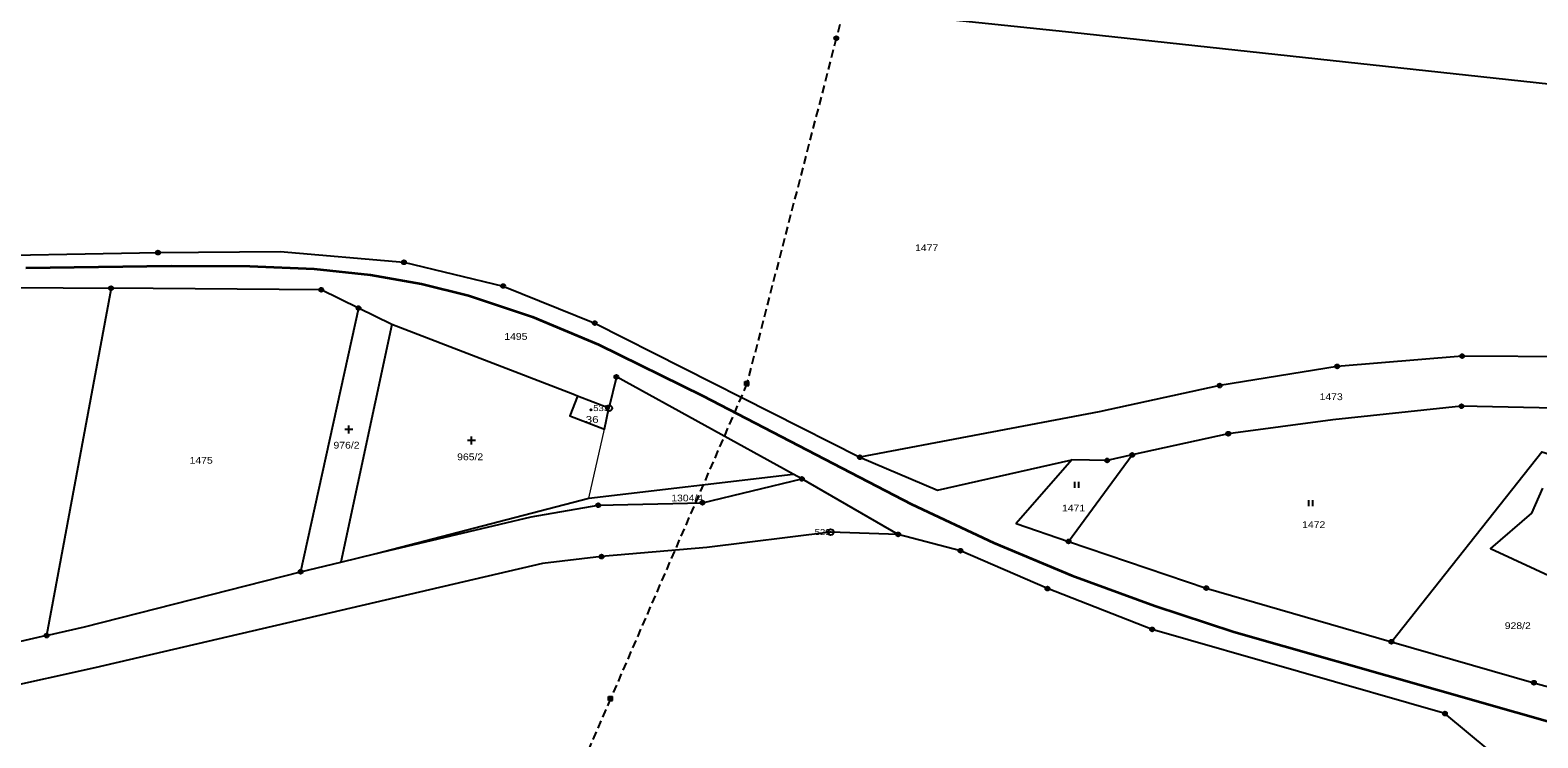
# Model space of a CAD drawing. Extents: x -872229 to -869198, y -1075981 to -1074329.
# Drawn here: x -871585.9 to -871207, y -1075387.5 to -1075209.5 of the extents above; entities that cross this region are included whole.
import ezdxf
from ezdxf.enums import TextEntityAlignment as Align

# ---------------------------------------------------------------- set-up
doc = ezdxf.new("R2010")
doc.units = 0
doc.header["$LTSCALE"] = 0.68
doc.linetypes.add('MEDIUM_DASHED', pattern=[4.5, 3, -1.5])
for name, color, linetype, lineweight in [('1', 7, 'Continuous', 25), ('3', 7, 'Continuous', 25), ('4', 7, 'Continuous', 13), ('5', 7, 'Continuous', 25), ('6', 7, 'Continuous', 25), ('8', 7, 'Continuous', 25)]:
    doc.layers.add(name, color=color, linetype=linetype, lineweight=lineweight)
doc.layers.add('2', color=7, linetype='Continuous')

msp = doc.modelspace()

# ---------------------------------------------------------------- linework, layer by layer
at = {"layer": '1'}
for p, q in [((-871391.97, -1075322.38), (-871394.16, -1075321.17)), ((-871367.76, -1075336.32), (-871391.97, -1075322.38)), ((-871517.94, -1075345.74), (-871507.87, -1075343.3))]:
    msp.add_line(p, q, dxfattribs=at)
for points in [[(-871152.53, -1075228.75), (-871324.15, -1075210.15), (-871498.95, -1075191.88), (-871564.6, -1075180.17), (-871590.36, -1075167.06), (-871608.79, -1075266.42)], [(-871673.37, -1075268.15), (-871670.8, -1075268.84), (-871646.86, -1075272.41), (-871613.89, -1075274.07), (-871565.58, -1075274.43)], [(-871608.79, -1075266.42), (-871553.79, -1075265.47), (-871523.09, -1075265.22), (-871491.97, -1075267.91), (-871467.05, -1075273.87), (-871444.01, -1075283.21), (-871377.38, -1075316.93)], [(-871503.38, -1075279.44), (-871512.76, -1075274.83), (-871565.58, -1075274.43), (-871581.77, -1075361.77)], [(-871495.01, -1075283.55), (-871503.38, -1075279.44), (-871517.94, -1075345.74)], [(-871495.01, -1075283.55), (-871507.87, -1075343.3), (-871498.97, -1075341.15)], [(-871448.37, -1075301.54), (-871449.54, -1075301.09), (-871495.01, -1075283.55)], [(-871197.94, -1075291.72), (-871226.01, -1075291.51), (-871257.41, -1075294.08), (-871286.96, -1075298.91), (-871317.28, -1075305.51), (-871377.38, -1075316.93)], [(-871394.16, -1075321.17), (-871438.58, -1075296.72), (-871440.45, -1075304.59)], [(-871198.89, -1075304.69), (-871226.19, -1075304.09), (-871258.51, -1075307.55), (-871284.79, -1075311.01), (-871308.94, -1075316.35)], [(-871243.8, -1075363.33), (-871206.01, -1075315.54), (-871202.96, -1075316.49), (-871198.89, -1075304.69)], [(-871377.38, -1075316.93), (-871357.91, -1075325.19), (-871324.12, -1075317.6)], [(-871324.12, -1075317.6), (-871338.12, -1075333.63), (-871324.93, -1075338.1), (-871308.94, -1075316.35)], [(-871308.94, -1075316.35), (-871315.25, -1075317.74), (-871324.12, -1075317.6)], [(-871498.97, -1075341.15), (-871445.51, -1075327.21), (-871394.16, -1075321.17)], [(-871498.97, -1075341.15), (-871459.98, -1075331.95), (-871443.14, -1075329), (-871416.95, -1075328.37), (-871391.97, -1075322.38)], [(-871205.8, -1075324.68), (-871208.57, -1075330.98), (-871218.91, -1075339.87), (-871180.67, -1075357.59)], [(-871367.76, -1075336.32), (-871384.74, -1075335.75), (-871415.81, -1075339.64), (-871442.3, -1075341.92), (-871457.12, -1075343.68), (-871569.63, -1075369.86), (-871593.96, -1075375.27), (-871613.49, -1075377.17), (-871630.54, -1075375.46), (-871654.44, -1075369.56), (-871683.36, -1075359.66)], [(-871212.24, -1075392.84), (-871218.94, -1075390.82), (-871230.33, -1075381.38), (-871303.93, -1075360.22), (-871330.24, -1075349.97), (-871352.11, -1075340.43), (-871367.76, -1075336.32)], [(-871581.77, -1075361.77), (-871595.26, -1075364.86), (-871610.89, -1075365.32), (-871627.46, -1075364.95), (-871651.19, -1075358.47), (-871705.48, -1075340.14)], [(-871324.93, -1075338.1), (-871290.33, -1075349.84), (-871243.8, -1075363.33)], [(-871581.77, -1075361.77), (-871572.27, -1075359.6), (-871517.94, -1075345.74)], [(-871243.8, -1075363.33), (-871207.98, -1075373.63), (-871201.2, -1075375.48), (-871200.62, -1075375.46)]]:
    msp.add_lwpolyline(points, dxfattribs=at)
msp.add_lwpolyline([(-871448.37, -1075301.54), (-871450.3, -1075306.53), (-871441.59, -1075309.84), (-871440.45, -1075304.59)], close=True, dxfattribs=at)
at = {"layer": '3'}
for p, q in [((-871504.829, -1075309.941), (-871506.831, -1075309.941)), ((-871505.83, -1075310.94), (-871505.83, -1075308.94)), ((-871473.959, -1075312.711), (-871475.961, -1075312.711)), ((-871474.96, -1075313.71), (-871474.96, -1075311.71)), ((-871323.381, -1075324.65), (-871323.381, -1075323.15)), ((-871322.38, -1075324.65), (-871322.38, -1075323.15)), ((-871264.561, -1075329.2), (-871264.561, -1075327.7)), ((-871263.56, -1075329.2), (-871263.56, -1075327.7))]:
    msp.add_line(p, q, dxfattribs=at)
at = {"layer": '4'}
msp.add_line((-871445.51, -1075327.21), (-871441.59, -1075309.84), dxfattribs=at)
at = {"layer": '5'}
msp.add_circle((-871444.9668, -1075305.0092), 0.175, dxfattribs=at)
at = {"layer": '6', "lineweight": 35}
for p, q in [((-871586.98, -1075269.26), (-871550.47, -1075268.77)), ((-871487.52, -1075273.3), (-871475.72, -1075276.29)), ((-871443.06, -1075288.59), (-871416.88, -1075301.49)), ((-871343.69, -1075338.47), (-871324.13, -1075346.64))]:
    msp.add_line(p, q, dxfattribs=at)
at = {"layer": '6', "linetype": 'MEDIUM_DASHED'}
msp.add_line((-871405.77, -1075298.4), (-871440.02, -1075377.58), dxfattribs=at)
at = {"layer": '6'}
for p, q in [((-871406.272, -1075297.899), (-871405.271, -1075297.899)), ((-871406.272, -1075298.899), (-871406.272, -1075297.899)), ((-871406.272, -1075298.099), (-871405.271, -1075298.099)), ((-871406.272, -1075298.299), (-871405.271, -1075298.299)), ((-871406.272, -1075298.499), (-871405.271, -1075298.499)), ((-871406.272, -1075298.699), (-871405.271, -1075298.699)), ((-871406.272, -1075298.899), (-871405.271, -1075298.899)), ((-871406.071, -1075298.899), (-871406.071, -1075297.899)), ((-871405.872, -1075298.899), (-871405.872, -1075297.899)), ((-871405.671, -1075298.899), (-871405.671, -1075297.899)), ((-871405.472, -1075298.899), (-871405.472, -1075297.899)), ((-871405.271, -1075298.899), (-871405.271, -1075297.899)), ((-871440.522, -1075377.079), (-871439.521, -1075377.079)), ((-871440.522, -1075378.079), (-871440.522, -1075377.079)), ((-871440.522, -1075377.279), (-871439.521, -1075377.279)), ((-871440.522, -1075377.479), (-871439.521, -1075377.479)), ((-871440.522, -1075377.679), (-871439.521, -1075377.679)), ((-871440.522, -1075377.879), (-871439.521, -1075377.879)), ((-871440.522, -1075378.079), (-871439.521, -1075378.079)), ((-871440.321, -1075378.079), (-871440.321, -1075377.079)), ((-871440.122, -1075378.079), (-871440.122, -1075377.079)), ((-871439.921, -1075378.079), (-871439.921, -1075377.079)), ((-871439.722, -1075378.079), (-871439.722, -1075377.079)), ((-871439.521, -1075378.079), (-871439.521, -1075377.079))]:
    msp.add_line(p, q, dxfattribs=at)
at = {"layer": '6', "linetype": 'MEDIUM_DASHED'}
for points in [[(-871372.59, -1075169.57), (-871383.31, -1075211.56), (-871405.77, -1075298.4)], [(-871440.02, -1075377.58), (-871476.16, -1075460.89), (-871517.14, -1075554.83)]]:
    msp.add_lwpolyline(points, dxfattribs=at)
at = {"layer": '6', "lineweight": 35}
for points in [[(-871550.47, -1075268.77), (-871530.68, -1075268.88), (-871514.5, -1075269.55)], [(-871514.5, -1075269.55), (-871500.36, -1075271.03), (-871487.52, -1075273.3)], [(-871475.72, -1075276.29), (-871459.68, -1075281.62), (-871443.06, -1075288.59)], [(-871416.88, -1075301.49), (-871364.43, -1075328.75), (-871343.69, -1075338.47)], [(-871324.13, -1075346.64), (-871303.26, -1075354.3), (-871283.38, -1075360.82)], [(-871283.38, -1075360.82), (-871232.19, -1075375.42), (-871192.83, -1075386.61)]]:
    msp.add_lwpolyline(points, dxfattribs=at)
at = {"layer": '6'}
for radius in [0.5, 0.4, 0.3, 0.2, 0.1]:
    msp.add_circle((-871383.3134, -1075211.5599), radius, dxfattribs=at)
at = {"layer": '8'}
for centre, radius in [((-871553.79, -1075265.4699), 0.5), ((-871553.79, -1075265.4699), 0.0303), ((-871491.97, -1075267.9099), 0.5), ((-871491.97, -1075267.9099), 0.0303), ((-871565.58, -1075274.4299), 0.5), ((-871565.58, -1075274.4299), 0.0303), ((-871512.76, -1075274.8299), 0.5), ((-871512.76, -1075274.8299), 0.0303), ((-871467.05, -1075273.8699), 0.5), ((-871467.05, -1075273.8699), 0.0303), ((-871503.38, -1075279.4399), 0.5), ((-871503.38, -1075279.4399), 0.0303), ((-871444.01, -1075283.2099), 0.5), ((-871444.01, -1075283.2099), 0.0303), ((-871226.01, -1075291.5099), 0.5), ((-871226.01, -1075291.5099), 0.0303), ((-871257.41, -1075294.0799), 0.5), ((-871257.41, -1075294.0799), 0.0303), ((-871438.58, -1075296.7199), 0.5), ((-871438.58, -1075296.7199), 0.0303), ((-871286.96, -1075298.9099), 0.5), ((-871286.96, -1075298.9099), 0.0303), ((-871440.39, -1075304.5798), 0.75), ((-871440.39, -1075304.5798), 0.03), ((-871226.19, -1075304.0899), 0.5), ((-871226.19, -1075304.0899), 0.0303), ((-871284.79, -1075311.0099), 0.5), ((-871284.79, -1075311.0099), 0.0303), ((-871377.38, -1075316.9299), 0.5), ((-871377.38, -1075316.9299), 0.0303), ((-871315.25, -1075317.7399), 0.5), ((-871315.25, -1075317.7399), 0.0303), ((-871308.94, -1075316.3499), 0.5), ((-871308.94, -1075316.3499), 0.0303), ((-871391.97, -1075322.3799), 0.5), ((-871391.97, -1075322.3799), 0.0303), ((-871443.14, -1075328.9999), 0.5), ((-871443.14, -1075328.9999), 0.0303), ((-871416.95, -1075328.3699), 0.5), ((-871416.95, -1075328.3699), 0.0303), ((-871384.74, -1075335.7498), 0.75), ((-871384.74, -1075335.7498), 0.03), ((-871367.76, -1075336.3199), 0.5), ((-871367.76, -1075336.3199), 0.0303), ((-871352.11, -1075340.4299), 0.5), ((-871352.11, -1075340.4299), 0.0303), ((-871324.93, -1075338.0999), 0.5), ((-871324.93, -1075338.0999), 0.0303), ((-871442.3, -1075341.9199), 0.5), ((-871442.3, -1075341.9199), 0.0303), ((-871517.94, -1075345.7399), 0.5), ((-871517.94, -1075345.7399), 0.0303), ((-871330.24, -1075349.9699), 0.5), ((-871330.24, -1075349.9699), 0.0303), ((-871290.33, -1075349.8399), 0.5), ((-871290.33, -1075349.8399), 0.0303), ((-871303.93, -1075360.2199), 0.5), ((-871581.77, -1075361.7699), 0.5), ((-871581.77, -1075361.7699), 0.0303), ((-871303.93, -1075360.2199), 0.0303), ((-871243.8, -1075363.3299), 0.5), ((-871243.8, -1075363.3299), 0.0303), ((-871207.98, -1075373.6299), 0.5), ((-871207.98, -1075373.6299), 0.0303), ((-871230.33, -1075381.3799), 0.5), ((-871230.33, -1075381.3799), 0.0303)]:
    msp.add_circle(centre, radius, dxfattribs=at)

# ---------------------------------------------------------------- texts
at = {"layer": '2'}
for s, width, p in [('1477', 1.15, (-871363.52, -1075265.11)), ('1495', 1.15, (-871466.75, -1075287.41)), ('1473', 1.15, (-871261.85, -1075302.57)), ('36', 1.3, (-871446.32, -1075308.28)), ('976/2', 1.15, (-871509.68, -1075314.75)), ('1475', 1.15, (-871545.84, -1075318.56)), ('965/2', 1.15, (-871478.6, -1075317.68)), ('1304/4', 1.15, (-871424.79, -1075328.02)), ('1471', 1.15, (-871326.59, -1075330.57)), ('1472', 1.15, (-871266.24, -1075334.73)), ('928/2', 1.15, (-871215.31, -1075360.14))]:
    msp.add_text(s, height=1.7, dxfattribs=dict(at, width=width)).set_placement(p)
at = {"layer": '8', "width": 1.2}
for s, p in [('533', (-871440.39, -1075305.33)), ('529', (-871384.74, -1075336.5))]:
    msp.add_text(s, height=1.5, dxfattribs=at).set_placement(p, align=Align.RIGHT)

doc.saveas('drawing.dxf')
